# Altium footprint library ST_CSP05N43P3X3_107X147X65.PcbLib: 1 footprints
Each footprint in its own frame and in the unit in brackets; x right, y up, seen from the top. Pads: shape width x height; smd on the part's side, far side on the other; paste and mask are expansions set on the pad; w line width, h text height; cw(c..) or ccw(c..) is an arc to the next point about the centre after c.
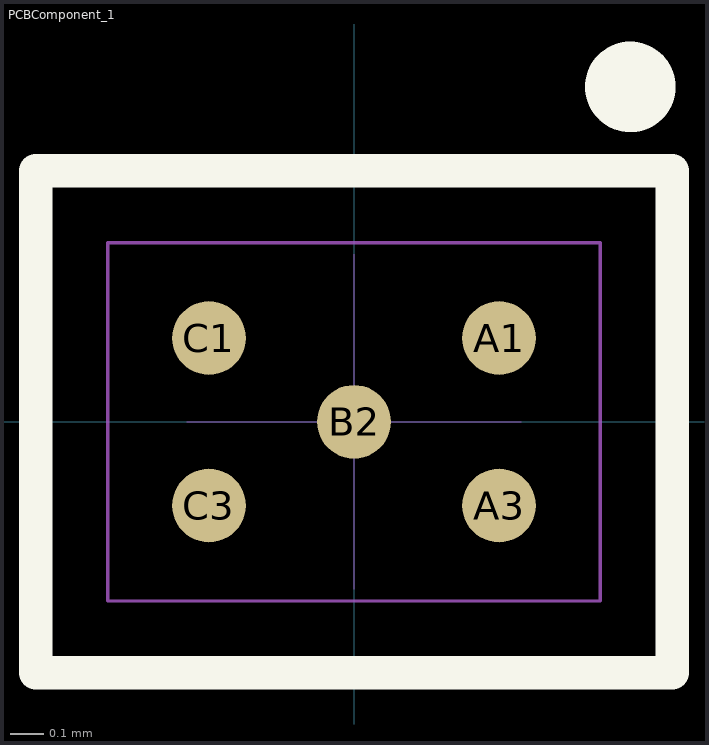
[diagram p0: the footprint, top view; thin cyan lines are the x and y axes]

## PCBComponent_1 [mm]
pads (5):
  round 0.22 smd paste-20 mask+0.06: A1(0.433,0.25) A3(0.433,-0.25) B2(0,0) C1(-0.433,0.25) C3(-0.433,-0.25)
Top Overlay:
  circle w0.2: c0.825,1 r0.035
  lines w0.1: -0.95,-0.75 -0.95,0.75 0.95,0.75 0.95,-0.75 -0.95,-0.75
Top Paste:
  rectangle: 0.268,-0.415 0.598,-0.085
  rectangle: -0.598,-0.415 -0.268,-0.085
  rectangle: -0.165,-0.165 0.165,0.165
  rectangle: 0.268,0.085 0.598,0.415
  rectangle: -0.598,0.085 -0.268,0.415
Mechanical 15:
  lines w0.001: -0.5,0 0.5,0 ; 0,-0.5 0,0.5
  lines w0.01: -0.735,-0.535 -0.735,0.535 0.735,0.535 0.735,-0.535 -0.735,-0.535
3D body: height 0.65, standoff 0.32, extent -0.735,-0.535 0.735,0.535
